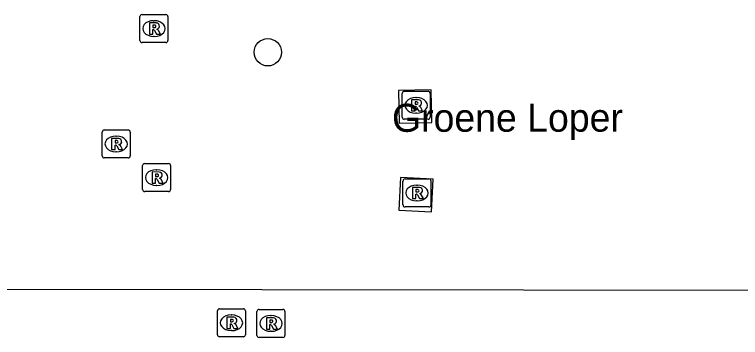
# Model space of a CAD drawing. Extents: x 161477 to 163040, y 383680 to 384868.
# Drawn here: x 162151.98 to 162177.92, y 384189.23 to 384200.76 of the extents above; entities that cross this region are included whole.
import ezdxf

# ---------------------------------------------------------------- set-up
doc = ezdxf.new("R2010")
doc.units = 0
for name, color, linetype in [('IMGEO_Boom', 7, 'Continuous'), ('IMGEO_Openbare_ruimte_label', 7, 'Continuous'), ('IMGEO_Rioolput', 7, 'Continuous'), ('IMGEO_Voetpad_open', 7, 'Continuous')]:
    doc.layers.add(name, color=color, linetype=linetype)

msp = doc.modelspace()

# ---------------------------------------------------------------- linework, layer by layer
at = {"layer": 'IMGEO_Boom'}
msp.add_circle((162161.028, 384199.414), 0.489, dxfattribs=at)
at = {"layer": 'IMGEO_Rioolput'}
for p, q in [((162156.458, 384199.837), (162156.458, 384200.689)), ((162156.533, 384200.763), (162157.385, 384200.763)), ((162157.459, 384200.689), (162157.459, 384199.837)), ((162156.946, 384200.543), (162156.971, 384200.543)), ((162156.969, 384199.983), (162156.944, 384199.983)), ((162157.385, 384199.763), (162156.533, 384199.763)), ((162165.904, 384198.02), (162166.756, 384198.02)), ((162165.829, 384197.094), (162165.829, 384197.946)), ((162166.317, 384197.8), (162166.342, 384197.8)), ((162166.83, 384197.946), (162166.83, 384197.094)), ((162166.34, 384197.24), (162166.315, 384197.24)), ((162166.756, 384197.02), (162165.904, 384197.02)), ((162155.109, 384195.714), (162155.109, 384196.566)), ((162155.184, 384196.64), (162156.036, 384196.64)), ((162156.11, 384196.566), (162156.11, 384195.714)), ((162155.597, 384196.42), (162155.622, 384196.42)), ((162155.62, 384195.86), (162155.595, 384195.86)), ((162156.036, 384195.64), (162155.184, 384195.64)), ((162156.629, 384195.439), (162157.481, 384195.439)), ((162156.554, 384194.513), (162156.554, 384195.365)), ((162157.042, 384195.219), (162157.067, 384195.219)), ((162157.555, 384195.365), (162157.555, 384194.513)), ((162165.934, 384194.89), (162166.786, 384194.89)), ((162157.065, 384194.659), (162157.04, 384194.659)), ((162165.859, 384193.964), (162165.859, 384194.816)), ((162166.347, 384194.67), (162166.372, 384194.67)), ((162166.86, 384194.816), (162166.86, 384193.964)), ((162157.481, 384194.439), (162156.629, 384194.439)), ((162166.37, 384194.11), (162166.345, 384194.11)), ((162166.786, 384193.89), (162165.934, 384193.89)), ((162159.303, 384190.252), (162160.155, 384190.252)), ((162160.715, 384190.228), (162161.567, 384190.228)), ((162159.228, 384189.326), (162159.228, 384190.178)), ((162159.716, 384190.032), (162159.741, 384190.032)), ((162160.229, 384190.178), (162160.229, 384189.326)), ((162160.64, 384189.302), (162160.64, 384190.154)), ((162161.128, 384190.008), (162161.153, 384190.008)), ((162161.641, 384190.154), (162161.641, 384189.302)), ((162159.739, 384189.472), (162159.714, 384189.472)), ((162161.151, 384189.448), (162161.126, 384189.448)), ((162160.155, 384189.252), (162159.303, 384189.252)), ((162161.567, 384189.228), (162160.715, 384189.228))]:
    msp.add_line(p, q, dxfattribs=at)
for points in [[(162156.458, 384199.837), (162156.458, 384200.689)], [(162156.533, 384200.763), (162157.385, 384200.763)], [(162157.459, 384200.689), (162157.459, 384199.837)], [(162157.047, 384200.461), (162156.795, 384200.463), (162156.795, 384200.063)], [(162156.973, 384200.382), (162156.919, 384200.382), (162156.919, 384200.301)], [(162156.795, 384200.063), (162156.919, 384200.063), (162156.919, 384200.225), (162156.93, 384200.225)], [(162156.919, 384200.301), (162156.971, 384200.301)], [(162156.977, 384200.196), (162157.048, 384200.063), (162157.188, 384200.063), (162157.123, 384200.189)], [(162157.385, 384199.763), (162156.533, 384199.763)], [(162165.904, 384198.02), (162166.756, 384198.02)], [(162165.829, 384197.094), (162165.829, 384197.946)], [(162166.83, 384197.946), (162166.83, 384197.094)], [(162166.418, 384197.718), (162166.166, 384197.72), (162166.166, 384197.32)], [(162166.166, 384197.32), (162166.29, 384197.32), (162166.29, 384197.482), (162166.301, 384197.482)], [(162166.344, 384197.639), (162166.29, 384197.639), (162166.29, 384197.558)], [(162166.29, 384197.558), (162166.342, 384197.558)], [(162166.348, 384197.453), (162166.419, 384197.32), (162166.559, 384197.32), (162166.494, 384197.446)], [(162166.756, 384197.02), (162165.904, 384197.02)], [(162155.109, 384195.714), (162155.109, 384196.566)], [(162155.184, 384196.64), (162156.036, 384196.64)], [(162156.11, 384196.566), (162156.11, 384195.714)], [(162155.698, 384196.338), (162155.446, 384196.34), (162155.446, 384195.94)], [(162155.624, 384196.259), (162155.57, 384196.259), (162155.57, 384196.178)], [(162155.446, 384195.94), (162155.57, 384195.94), (162155.57, 384196.102), (162155.581, 384196.102)], [(162155.57, 384196.178), (162155.622, 384196.178)], [(162155.628, 384196.073), (162155.699, 384195.94), (162155.839, 384195.94), (162155.774, 384196.066)], [(162156.036, 384195.64), (162155.184, 384195.64)], [(162156.629, 384195.439), (162157.481, 384195.439)], [(162156.554, 384194.513), (162156.554, 384195.365)], [(162157.555, 384195.365), (162157.555, 384194.513)], [(162157.143, 384195.137), (162156.891, 384195.139), (162156.891, 384194.739)], [(162156.891, 384194.739), (162157.015, 384194.739), (162157.015, 384194.901), (162157.026, 384194.901)], [(162157.069, 384195.058), (162157.015, 384195.058), (162157.015, 384194.977)], [(162157.015, 384194.977), (162157.067, 384194.977)], [(162165.934, 384194.89), (162166.786, 384194.89)], [(162157.073, 384194.872), (162157.144, 384194.739), (162157.284, 384194.739), (162157.219, 384194.865)], [(162165.859, 384193.964), (162165.859, 384194.816)], [(162166.86, 384194.816), (162166.86, 384193.964)], [(162157.481, 384194.439), (162156.629, 384194.439)], [(162166.448, 384194.588), (162166.196, 384194.59), (162166.196, 384194.19)], [(162166.374, 384194.509), (162166.32, 384194.509), (162166.32, 384194.428)], [(162166.32, 384194.428), (162166.372, 384194.428)], [(162166.196, 384194.19), (162166.32, 384194.19), (162166.32, 384194.352), (162166.331, 384194.352)], [(162166.378, 384194.323), (162166.449, 384194.19), (162166.589, 384194.19), (162166.524, 384194.316)], [(162166.786, 384193.89), (162165.934, 384193.89)], [(162159.303, 384190.252), (162160.155, 384190.252)], [(162160.715, 384190.228), (162161.567, 384190.228)], [(162159.228, 384189.326), (162159.228, 384190.178)], [(162160.229, 384190.178), (162160.229, 384189.326)], [(162160.64, 384189.302), (162160.64, 384190.154)], [(162161.641, 384190.154), (162161.641, 384189.302)], [(162159.817, 384189.95), (162159.565, 384189.952), (162159.565, 384189.552)], [(162159.565, 384189.552), (162159.689, 384189.552), (162159.689, 384189.714), (162159.7, 384189.714)], [(162159.743, 384189.871), (162159.689, 384189.871), (162159.689, 384189.79)], [(162159.689, 384189.79), (162159.741, 384189.79)], [(162161.229, 384189.926), (162160.977, 384189.928), (162160.977, 384189.528)], [(162161.155, 384189.847), (162161.101, 384189.847), (162161.101, 384189.766)], [(162161.101, 384189.766), (162161.153, 384189.766)], [(162159.747, 384189.685), (162159.818, 384189.552), (162159.958, 384189.552), (162159.893, 384189.678)], [(162160.977, 384189.528), (162161.101, 384189.528), (162161.101, 384189.69), (162161.112, 384189.69)], [(162161.159, 384189.661), (162161.23, 384189.528), (162161.37, 384189.528), (162161.305, 384189.654)], [(162160.155, 384189.252), (162159.303, 384189.252)], [(162161.567, 384189.228), (162160.715, 384189.228)]]:
    msp.add_lwpolyline(points, dxfattribs=at)
for centre, radius, start, end in [((162156.535, 384200.687), 0.0765, 91.552, 178.448), ((162156.535, 384200.687), 0.0765, 91.552, 178.448), ((162157.383, 384200.687), 0.0765, 1.552, 88.448), ((162157.383, 384200.687), 0.0765, 1.552, 88.448), ((162156.979, 384200.286), 0.0964, 77.0061, 93.1865), ((162156.993, 384200.343), 0.0378, 276.6634, 79.6772), ((162157.046, 384200.351), 0.109, 350.3612, 89.416), ((162157.044, 384200.351), 0.112, 277.5842, 350.9817), ((162156.929, 384200.172), 0.0533, 26.0293, 88.6989), ((162156.955, 384200.49), 0.19, 274.7715, 282.9687), ((162157.028, 384200.136), 0.108, 29.5134, 73.7905), ((162156.535, 384199.839), 0.0765, 181.552, 268.448), ((162156.535, 384199.839), 0.0765, 181.552, 268.448), ((162157.383, 384199.839), 0.0765, 271.552, 358.448), ((162157.383, 384199.839), 0.0765, 271.552, 358.448), ((162165.906, 384197.944), 0.0765, 91.552, 178.448), ((162165.906, 384197.944), 0.0765, 91.552, 178.448), ((162166.754, 384197.944), 0.0765, 1.552, 88.448), ((162166.754, 384197.944), 0.0765, 1.552, 88.448), ((162166.3, 384197.429), 0.0533, 26.0293, 88.6989), ((162166.326, 384197.747), 0.19, 274.7715, 282.9687), ((162166.35, 384197.543), 0.0964, 77.0061, 93.1865), ((162166.364, 384197.6), 0.0378, 276.6634, 79.6772), ((162166.417, 384197.608), 0.109, 350.3612, 89.416), ((162166.415, 384197.608), 0.112, 277.5842, 350.9817), ((162166.399, 384197.393), 0.108, 29.5134, 73.7905), ((162165.906, 384197.096), 0.0765, 181.552, 268.448), ((162165.906, 384197.096), 0.0765, 181.552, 268.448), ((162166.754, 384197.096), 0.0765, 271.552, 358.448), ((162166.754, 384197.096), 0.0765, 271.552, 358.448), ((162155.186, 384196.564), 0.0765, 91.552, 178.448), ((162155.186, 384196.564), 0.0765, 91.552, 178.448), ((162156.034, 384196.564), 0.0765, 1.552, 88.448), ((162156.034, 384196.564), 0.0765, 1.552, 88.448), ((162155.606, 384196.367), 0.19, 274.7715, 282.9687), ((162155.63, 384196.163), 0.0964, 77.0061, 93.1865), ((162155.644, 384196.22), 0.0378, 276.6634, 79.6772), ((162155.697, 384196.228), 0.109, 350.3612, 89.416), ((162155.695, 384196.228), 0.112, 277.5842, 350.9817), ((162155.58, 384196.049), 0.0533, 26.0293, 88.6989), ((162155.679, 384196.013), 0.108, 29.5134, 73.7905), ((162155.186, 384195.716), 0.0765, 181.552, 268.448), ((162155.186, 384195.716), 0.0765, 181.552, 268.448), ((162156.034, 384195.716), 0.0765, 271.552, 358.448), ((162156.034, 384195.716), 0.0765, 271.552, 358.448), ((162156.631, 384195.363), 0.0765, 91.552, 178.448), ((162156.631, 384195.363), 0.0765, 91.552, 178.448), ((162157.479, 384195.363), 0.0765, 1.552, 88.448), ((162157.479, 384195.363), 0.0765, 1.552, 88.448), ((162157.025, 384194.848), 0.0533, 26.0293, 88.6989), ((162157.051, 384195.166), 0.19, 274.7715, 282.9687), ((162157.075, 384194.962), 0.0964, 77.0061, 93.1865), ((162157.089, 384195.019), 0.0378, 276.6634, 79.6772), ((162157.142, 384195.027), 0.109, 350.3612, 89.416), ((162157.14, 384195.027), 0.112, 277.5842, 350.9817), ((162157.124, 384194.812), 0.108, 29.5134, 73.7905), ((162165.936, 384194.814), 0.0765, 91.552, 178.448), ((162165.936, 384194.814), 0.0765, 91.552, 178.448), ((162166.784, 384194.814), 0.0765, 1.552, 88.448), ((162166.784, 384194.814), 0.0765, 1.552, 88.448), ((162156.631, 384194.515), 0.0765, 181.552, 268.448), ((162156.631, 384194.515), 0.0765, 181.552, 268.448), ((162157.479, 384194.515), 0.0765, 271.552, 358.448), ((162157.479, 384194.515), 0.0765, 271.552, 358.448), ((162166.356, 384194.617), 0.19, 274.7715, 282.9687), ((162166.38, 384194.413), 0.0964, 77.0061, 93.1865), ((162166.394, 384194.47), 0.0378, 276.6634, 79.6772), ((162166.447, 384194.478), 0.109, 350.3612, 89.416), ((162166.445, 384194.478), 0.112, 277.5842, 350.9817), ((162166.429, 384194.263), 0.108, 29.5134, 73.7905), ((162166.33, 384194.299), 0.0533, 26.0293, 88.6989), ((162165.936, 384193.966), 0.0765, 181.552, 268.448), ((162165.936, 384193.966), 0.0765, 181.552, 268.448), ((162166.784, 384193.966), 0.0765, 271.552, 358.448), ((162166.784, 384193.966), 0.0765, 271.552, 358.448), ((162159.305, 384190.176), 0.0765, 91.552, 178.448), ((162159.305, 384190.176), 0.0765, 91.552, 178.448), ((162160.153, 384190.176), 0.0765, 1.552, 88.448), ((162160.153, 384190.176), 0.0765, 1.552, 88.448), ((162160.717, 384190.152), 0.0765, 91.552, 178.448), ((162160.717, 384190.152), 0.0765, 91.552, 178.448), ((162161.565, 384190.152), 0.0765, 1.552, 88.448), ((162161.565, 384190.152), 0.0765, 1.552, 88.448), ((162159.699, 384189.661), 0.0533, 26.0293, 88.6989), ((162159.725, 384189.979), 0.19, 274.7715, 282.9687), ((162159.749, 384189.775), 0.0964, 77.0061, 93.1865), ((162159.763, 384189.832), 0.0378, 276.6634, 79.6772), ((162159.816, 384189.84), 0.109, 350.3612, 89.416), ((162159.814, 384189.84), 0.112, 277.5842, 350.9817), ((162159.798, 384189.625), 0.108, 29.5134, 73.7905), ((162161.137, 384189.955), 0.19, 274.7715, 282.9687), ((162161.161, 384189.751), 0.0964, 77.0061, 93.1865), ((162161.175, 384189.808), 0.0378, 276.6634, 79.6772), ((162161.228, 384189.816), 0.109, 350.3612, 89.416), ((162161.226, 384189.816), 0.112, 277.5842, 350.9817), ((162161.21, 384189.601), 0.108, 29.5134, 73.7905), ((162161.111, 384189.637), 0.0533, 26.0293, 88.6989), ((162159.305, 384189.328), 0.0765, 181.552, 268.448), ((162159.305, 384189.328), 0.0765, 181.552, 268.448), ((162160.153, 384189.328), 0.0765, 271.552, 358.448), ((162160.153, 384189.328), 0.0765, 271.552, 358.448), ((162160.717, 384189.304), 0.0765, 181.552, 268.448), ((162160.717, 384189.304), 0.0765, 181.552, 268.448), ((162161.565, 384189.304), 0.0765, 271.552, 358.448), ((162161.565, 384189.304), 0.0765, 271.552, 358.448)]:
    msp.add_arc(centre, radius, start, end, dxfattribs=at)
for centre, major_axis, ratio, start_param, end_param in [((162156.945, 384200.263), (-0.387, 0.002), 0.722429, 4.712389, 7.853982), ((162156.97, 384200.263), (-0.39, 0.002), 0.717154, 1.570796, 4.712389), ((162166.316, 384197.52), (-0.387, 0.002), 0.722429, 4.712389, 7.853982), ((162166.341, 384197.52), (-0.39, 0.002), 0.717154, 1.570796, 4.712389), ((162155.596, 384196.14), (-0.387, 0.002), 0.722429, 4.712389, 7.853982), ((162155.621, 384196.14), (-0.39, 0.002), 0.717154, 1.570796, 4.712389), ((162157.041, 384194.939), (-0.387, 0.002), 0.722429, 4.712389, 7.853982), ((162157.066, 384194.939), (-0.39, 0.002), 0.717154, 1.570796, 4.712389), ((162166.346, 384194.39), (-0.387, 0.002), 0.722429, 4.712389, 7.853982), ((162166.371, 384194.39), (-0.39, 0.002), 0.717154, 1.570796, 4.712389), ((162159.715, 384189.752), (-0.387, 0.002), 0.722429, 4.712389, 7.853982), ((162159.74, 384189.752), (-0.39, 0.002), 0.717154, 1.570796, 4.712389), ((162161.127, 384189.728), (-0.387, 0.002), 0.722429, 4.712389, 7.853982), ((162161.152, 384189.728), (-0.39, 0.002), 0.717154, 1.570796, 4.712389)]:
    msp.add_ellipse(centre, major_axis=major_axis, ratio=ratio, start_param=start_param, end_param=end_param, dxfattribs=at)
at = {"layer": 'IMGEO_Voetpad_open'}
for points in [[(162166.868, 384198.078), (162165.699, 384198.054), (162165.723, 384196.886), (162166.892, 384196.909), (162166.868, 384198.078)], [(162166.939, 384194.882), (162165.771, 384194.946), (162165.706, 384193.777), (162166.875, 384193.714), (162166.939, 384194.882)], [(162104.654, 384191.016), (162188.881, 384190.9), (162188.873, 384192.38)]]:
    msp.add_lwpolyline(points, dxfattribs=at)

# ---------------------------------------------------------------- texts
at = {"layer": 'IMGEO_Openbare_ruimte_label'}
msp.add_text('Groene Loper', height=1, rotation=0.0573, dxfattribs=at).set_placement((162165.467, 384196.573))

doc.saveas('drawing.dxf')
